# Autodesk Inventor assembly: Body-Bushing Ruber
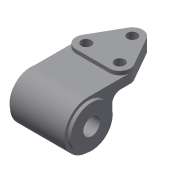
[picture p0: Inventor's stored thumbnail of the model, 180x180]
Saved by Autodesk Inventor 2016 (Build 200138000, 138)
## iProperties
Created: 2011-07
Part Number: Body-Bushing Ruber
Document SubType Name: Assembly
Designer: CadCim
Author: CadCim
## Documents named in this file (3)
- D:\KAVITA\Autodesk Inventor_ 2016 Project_Kavita\Inventor_Part Files\Inventor_2016_tut\c09_Inv_tut_2016\c09_tut03_inv\Anti Vibration Mount\Body-Bushing Ruber.iam
- D:\KAVITA\Autodesk Inventor_ 2016 Project_Kavita\Inventor_Part Files\Inventor_2016_tut\c09_Inv_tut_2016\c09_tut03_inv\Anti Vibration Mount\Body.ipt
- D:\KAVITA\Autodesk Inventor_ 2016 Project_Kavita\Inventor_Part Files\Inventor_2016_tut\c09_Inv_tut_2016\c09_tut03_inv\Anti Vibration Mount\Bushing Rubber.ipt
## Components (3 placed, 2 different names)
1. Body:1 — Insert:1, Insert:2
2. Bushing Rubber:1 — Insert:1
3. Bushing Rubber:2 — Insert:2
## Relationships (2: Insert 2)
- Insert:1: Body:1 ↔ Bushing Rubber:1
- Insert:2: Body:1 ↔ Bushing Rubber:2
